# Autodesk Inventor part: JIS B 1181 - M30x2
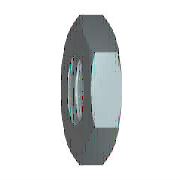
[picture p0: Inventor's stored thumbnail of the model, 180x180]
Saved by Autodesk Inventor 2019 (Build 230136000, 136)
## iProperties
IsCustomPart: 0
Created: 2017-02
Part Number: JIS B 1181 - M30x2
Material: 鋼、軟鋼
Description: 六角低ナット - 両面取り(部品等級B) - 細目ねじ
Document SubType Name: Modeling
Standard: JIS B 1181
Designer: shimont
Standard Revision: 2014
Standards Organization: JIS
Language: ja-JP
Size Designation: M30x2
Categories: <MemberInstance><Categories><Category DisplayName="締結器具" InternalName="e4da775c-781d-43d5-af7c-5136215cf5a6" Mnemonic="FSTN"><Category DisplayName="ナット" Interna
Density: 7.85 g/cm^3
Appearance: 半つや出し
Mass: 141.763 g
Surface Area: 58.7829 cm^2
Volume: 18.059 cm^3
Author: shimont
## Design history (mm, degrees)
node "MSC_A1"
node "MSC_PT1"
node "MSC_PT2"
node "MSC_PF1"
body "Solid1"
sketch "スケッチ1"
  geometry: L1 (23, 13.279)-(23, -13.279); L2 (23, -13.279)-(0, -26.558); L3 (0, -26.558)-(-23, -13.279); L4 (-23, -13.279)-(-23, 13.279); L5 (-23, 13.279)-(0, 26.558); L6 (0, 26.558)-(23, 13.279); C1 r 23 at (0, 0); 2 further points
  constraints: 12 end point, 2 coincident, 1 centre point, 1 tangent, 1 vertical, 11 other
  dimensions: "d0" = 46 diameter of C1 (= ParS)
extrude "押し出し1" new body sketch "スケッチ1" distance "d1" = 15 (= M); taper "d2" = 0 deg
sketch "スケッチ2"
  geometry: L1 (-23, 13.279)-(0, 26.558) reference; L2 (0, -26.558)-(-23, -13.279) reference; L3 (-23, 13.279)-(23, -13.279); L4 (-23, -13.279)-(23, 13.279); 1 further point
  constraints: 4 end point, 2 midpoint, 2 parallel
hole "穴1" sketch "スケッチ2" diameter "d3" = 27.835; stored, may be unused: countersink angle "d7" = 90 deg, drill point angle "d9" = 118 deg; dims "d4" = 6, "d5" = 4, "d6" = 2, "d8" = 8
chamfer "面取り1" distance "d10" = 1 (= 0.5 x PTC); stored, may be unused: second distance "d11" = 2, angle "d12" = 45 deg
revolve "回転1" stored, may be unused: angle "d15" = 90 deg
sketch "スケッチ3"
  geometry: L1 (-26.558, 15)-(-26.558, 12.946); L2 (-26.558, 12.946)-(-23, 15); L3 (-23, 15)-(-26.558, 15); L4 (-26.558, 2.054)-(-26.558, 0); L5 (-26.558, 0)-(-23, 0); L6 (-23, 0)-(-26.558, 2.054); L7 (0, 18)-(0, -3) reference; L8 (-13.279, 15)-(-26.558, 15) reference; L9 (-13.279, 0)-(-26.558, 0) reference; L10 (-26.558, 0)-(-26.558, 15) reference
  constraints: 12 end point, 4 collinear, 3 perpendicular, 2 equal length, 1 vertical
  dimensions: "d13" = 30 deg angle of L2 L3; "d14" = 23 distance from line of L2.end L7 (= 0.5 x ParS)
other parameters: "ParS" = 46 [user parameter; used in 2 equation terms], "M" = 15 [user parameter; used in 1 equation term], "PTC" = 2 [user parameter; used in 1 equation term], "d17" = 0, "d18" = 0, "d19" = 0, "d20" = 0, "d21" = 0, "d22" = 0, "d23" = 0
